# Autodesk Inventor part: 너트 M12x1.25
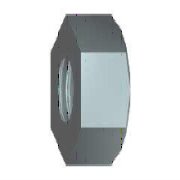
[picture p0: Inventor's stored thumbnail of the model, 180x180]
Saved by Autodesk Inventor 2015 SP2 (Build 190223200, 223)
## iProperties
IsCustomPart: 0
Created: 2015-12
Part Number: 너트 M12x1.25
Material: 스테인리스강
Description: 6각 너트
Document SubType Name: Modeling
Standard: KS B 1012
Designer: mdu
Standards Organization: KS
Language: ko-KR
Size Designation: M12x1.25
Categories: <MemberInstance><Categories><Category DisplayName="조임쇠" InternalName="e4da775c-781d-43d5-af7c-5136215cf5a6" Mnemonic="FSTN"><Category DisplayName="너트" InternalN
Density: 8.08 g/cm^3
Appearance: 반광택
Author: mdu
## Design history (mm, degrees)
sketch "스케치1"
  geometry: L1 (10.97, 0)-(5.485, -9.5); L2 (5.485, -9.5)-(-5.485, -9.5); L3 (-5.485, -9.5)-(-10.97, 0); L4 (-10.97, 0)-(-5.485, 9.5); L5 (-5.485, 9.5)-(5.485, 9.5); L6 (5.485, 9.5)-(10.97, 0); 2 further points
  constraints: 12 end point, 1 coincident, 1 horizontal, 11 other
  dimensions: "d0" = 21.93931 distance of L1.start L3.end (= 1.1547 x SW)
extrude "본체" new body sketch "스케치1" distance "d1" = 10 (= KOH); taper "d2" = 0 deg
sketch "스케치2"
  geometry: 1 further point
hole "스레드" sketch "스케치2" diameter "d6" = 10.647; stored, may be unused: countersink angle "d10" = 82 deg, drill point angle "d12" = 118 deg; dims "d7" = 12.7, "d8" = 9.525, "d9" = 6.35, "d11" = 19.05
sketch "스케치3"
  geometry: L1 (0, 10.97)-(10, 10.97) reference; L2 (10, 5.485)-(10, 10.97) reference; L3 (-2, 0)-(12, 0) reference; L4 (9.151, 10.97)-(10, 9.5)
  constraints: 2 end point, 2 point on line
  dimensions: "d3" = 19 diameter of L4.end L3 (= SW01); "d4" = 30 deg angle of L2 L4 (= ANG2)
revolve "모따기3" sketch "스케치3" stored, may be unused: angle "d5" = 90 deg
workaxis "Work Axis1"
workplane "Work Plane1"
body "Solid1"
chamfer "모따기1" distance "d13" = 0.67658 (= -0.5 x GD1 + 0.5 x NND); stored, may be unused: angle "d14" = 30 deg, second distance "d21" = 0.67658 (= -0.5 x GD1 + 0.5 x NND)
chamfer "모따기2" distance "d15" = 0.67658 (= -0.5 x GD1 + 0.5 x NND); stored, may be unused: angle "d16" = 30 deg, second distance "d22" = 0.67658 (= -0.5 x GD1 + 0.5 x NND)
other parameters: "ANG2" = 30 deg [user parameter; used in 1 equation term], "NND" = 12 [user parameter; used in 4 equation terms], "KOH" = 10 [user parameter; used in 1 equation term], "SW" = 19 [user parameter; used in 3 equation terms], "SW01" = 19 (= SW) [user parameter; used in 1 equation term], "GD1" = 10.64684 (computed from THREADDIA, PTC, TOA) [user parameter; used in 4 equation terms], "d19" = 0, "d20" = 0, "d24" = 0, "d25" = 0, "GUL" = 0.67658 (= 0.541266 x PTC) [user parameter], "TPU" = 8 (computed from PTC) [user parameter], "TOA" = 30 deg [user parameter; used in 1 equation term], "PTC" = 1.25 [user parameter; used in 4 equation terms], "E0" = 21.945 (= 1.155 x SW) [user parameter], "THREADDIA" = 12 [user parameter; used in 1 equation term], "GAL" = 0.67658 (= 0.541266 x PTC) [user parameter]
